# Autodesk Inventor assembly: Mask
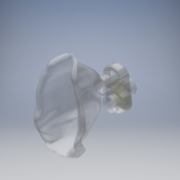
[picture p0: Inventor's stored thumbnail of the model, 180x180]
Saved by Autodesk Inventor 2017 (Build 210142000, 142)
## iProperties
Created: 2020-03
Part Number: Mask
Description: SolidWorks IGES file using analytic representation for surfaces
Document SubType Name: Assembly
Designer: user
Sending System: SolidWorks 2014
Preprocessor: SolidWorks 2014
Minimum Resolution: 0.0
Sending System Product ID: assembly.SLDASM
Receiving System Product ID: assembly.SLDASM
Sent Units: Millimeter
Translation Standard: IGES 5.3
Model Creation Time: 2020-03-21
Author: usuario
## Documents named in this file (5)
- C:\Users\user\Documents\Inventor\Home Ventilator CPAP\Mask.iam
- C:\Users\user\Documents\Inventor\MASK\medical mask.ipt
- C:\Users\user\Documents\Inventor\MASK\BODY VALVE.ipt
- C:\Users\user\Documents\Inventor\MASK\flap.ipt
- C:\Users\user\Documents\Inventor\MASK\BODY VALVE 1.ipt
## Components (4 placed, 4 different names)
1. medical mask
2. BODY VALVE
3. flap
4. BODY VALVE 1
